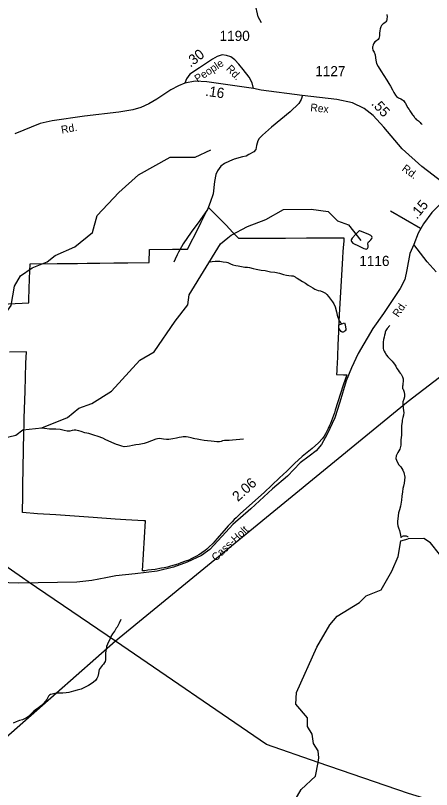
# Model space of a CAD drawing. Extents: x 2001466 to 2224147, y 644118 to 847247.
# Drawn here: x 2032407 to 2037525, y 669371 to 678885 of the extents above; entities that cross this region are included whole.
import ezdxf

# ---------------------------------------------------------------- set-up
doc = ezdxf.new("R2010")
doc.units = 0
for name, color, linetype in [('Exist Boundary Political City Limit New', 7, 'Continuous'), ('Exist Hydrographic Creek Single Shore', 7, 'Continuous'), ('Exist Hydrographic Misc Water Feature', 7, 'Continuous'), ('Exist Road Non-System Type 51', 7, 'Continuous'), ('Exist Road Secondary Mileage Hundredths English Label', 7, 'Continuous'), ('Exist Road Secondary Type 51 Attributed', 7, 'Continuous'), ('Exist Road Secondary Type 51 Label', 7, 'Continuous'), ('Exist Road Secondary Type 51 Number Label', 7, 'Continuous'), ('Exist Utilities Electrical Transmission Line', 7, 'Continuous'), ('Map Preparation Boundary City Limit Buffer Line', 7, 'Continuous')]:
    doc.layers.add(name, color=color, linetype=linetype)

msp = doc.modelspace()

# ---------------------------------------------------------------- linework, layer by layer
at = {"layer": 'Exist Boundary Political City Limit New'}
for points in [[(2032150.1, 675331.9), (2032570.6, 675351.3), (2032577.6, 675564.2), (2032579.2, 675608.3), (2032581.2, 675652.5), (2032588.4, 675832.8), (2032920.9, 675835.7), (2033170.2, 675837.9), (2033288, 675838.9), (2033445, 675840.2), (2033616.8, 675842.8), (2033788.5, 675845.2), (2034053.1, 675846.8), (2034057.5, 676010.3), (2034338.1, 676011.2), (2034412.5, 676011), (2034523.8, 676010.7), (2034656.9, 676273.8), (2034692.4, 676345.8), (2034781.1, 676524.9), (2035000, 676306.8), (2035082.4, 676217.2), (2035101.6, 676197.2)], [(2035101.6, 676197.2), (2035151.1, 676145.9), (2035232.5, 676147.4), (2035279.9, 676148.2), (2035730.8, 676149.4), (2035985.9, 676151.8), (2036075, 676151.7), (2036147.2, 676153), (2036238.4, 676152.8), (2036354.1, 676153.6), (2036385, 676153.5), (2036447.4, 676153.2), (2036446.6, 676141.7), (2036444.8, 676114.5), (2036438.8, 676028), (2036435.9, 675985.7), (2036430.5, 675903.8), (2036389.4, 675204.8), (2036384.8, 675113.8), (2036382.8, 675057), (2036380.8, 675000), (2036373.2, 674832), (2036371, 674779.9), (2036369.9, 674753.5), (2036369.8, 674750.8), (2036369.4, 674742.4), (2036366.8, 674679.1), (2036364.1, 674617.3), (2036360.4, 674540.9), (2036359.1, 674515.2), (2036357.6, 674470.4), (2036440.8, 674469), (2036442.1, 674469), (2036483.6, 674469.1), (2036437.8, 674340.8), (2036370.8, 674137.8), (2036340.8, 674033.2), (2036330.1, 674000), (2036319, 673967), (2036306.9, 673934.3), (2036294.4, 673901.8), (2036281, 673869.7), (2036267, 673837.8), (2036252.2, 673806.2), (2036237, 673775), (2036220.8, 673744.1), (2036204.2, 673713.5), (2036184.5, 673683.5), (2036136.5, 673630.5), (2036057.2, 673561.1), (2036018.1, 673528.9), (2035935, 673463.4), (2035841.5, 673379.3), (2035743.8, 673284.9), (2035656.2, 673200.5), (2035465.6, 673022.3), (2035175.2, 672761.7), (2035123.8, 672712.1), (2035097.2, 672688), (2035071.5, 672663), (2035059, 672650.1), (2035034.8, 672623.6), (2035023, 672610), (2035000, 672582.1), (2034890.5, 672455.7), (2034861.5, 672424.3), (2034837.6, 672399), (2034786.2, 672348.5), (2034759.6, 672323.8), (2034741.1, 672308.4), (2034701.9, 672278.5), (2034682.9, 672265.9), (2034663.5, 672254.1), (2034635.1, 672237.6), (2034569.6, 672204.4), (2034538.2, 672191.7), (2034498, 672177.5), (2034439.6, 672155.6), (2034403.4, 672142.7), (2034312.9, 672115), (2034276.8, 672105.4), (2034238, 672095.6), (2034205.6, 672089.5), (2034124, 672076.8), (2034078.8, 672070.1), (2034035.8, 672065.3), (2033998.1, 672059.7), (2033978.5, 672058), (2033971.2, 672056.9), (2034007.8, 672671.5), (2033987.2, 672672.8), (2033765.9, 672686.6), (2033631.9, 672695.6), (2033365.2, 672713.5), (2032904.9, 672745.6), (2032679.5, 672761.1), (2032494.5, 672773.8), (2032498.1, 672982.8), (2032499.9, 673106.6), (2032511.4, 673758.1)], [(2032511.4, 673758.1), (2032513.8, 673848.8), (2032516.1, 673935.4), (2032526, 674266.1), (2032537, 674611.6), (2032542, 674748.9), (2032335.8, 674746.7)]]:
    msp.add_lwpolyline(points, dxfattribs=at)
at = {"layer": 'Exist Hydrographic Creek Single Shore'}
for points in [[(2036129.8, 669704.3), (2036140.5, 669762), (2036131.5, 669844.3), (2036073.5, 669937.3), (2036056.5, 670052.5), (2035998.6, 670145.5), (2035998.6, 670253.8), (2035856.5, 670420.7), (2035864.5, 670561.7), (2036114.5, 671120.9), (2036272.6, 671393.3), (2036364.7, 671503), (2036639.6, 671671.3), (2036722.7, 671751.6), (2036905.6, 671826.6), (2037038.7, 672053.6), (2037113.7, 672235.8), (2037146.5, 672428.7), (2037236.1, 672453.3)], [(2037906.6, 671698), (2037831.6, 671732.4), (2037772.5, 671795.9), (2037722.5, 671997.1), (2037622.6, 672264.9), (2037513.6, 672404.9), (2037430.5, 672455.7), (2037236.1, 672453.3)], [(2034758.5, 668061.1), (2034941.6, 668228), (2034949.6, 668401.7), (2034982.6, 668453.5), (2035274.6, 668634.6), (2035449.5, 668854.2), (2035682.4, 668961), (2035923.6, 669369.5), (2036098.5, 669536.5), (2036129.8, 669704.3)]]:
    msp.add_lwpolyline(points, dxfattribs=at)
at = {"layer": 'Exist Hydrographic Misc Water Feature'}
msp.add_line((2032896.7, 675934.3), (2033137.7, 676040.6), dxfattribs=at)
for points in [[(2035435.8, 678792.5), (2035393.7, 678868.9), (2035318.9, 679201.7), (2035210.8, 679325.4), (2034976.9, 679451.5), (2034768.9, 679491.8), (2034376.9, 679466.9), (2034276.8, 679492), (2033843.9, 679408.9), (2033343.8, 679209), (2033026.8, 679274.6), (2032685.8, 679307.7), (2032218.9, 679382.8), (2031902.9, 679356.5), (2031718.8, 679291.3), (2031568.9, 679182.8), (2031377.8, 679157.2), (2031260.9, 679107), (2030952.9, 679090.3), (2030835.8, 679122.2), (2030419.8, 679097.8), (2030169.8, 678981.5), (2029908.9, 678947.4)], [(2036976.7, 678896.5), (2036978.8, 678868.5), (2036976.7, 678844), (2036974.7, 678832.6), (2036970.6, 678818.7), (2036964.8, 678808.2), (2036956.8, 678800.1), (2036938.6, 678788.2), (2036926.9, 678778.6), (2036910.9, 678760.1), (2036902.7, 678746.2), (2036892.9, 678720.2), (2036889, 678696.5), (2036887.1, 678666.2), (2036885.1, 678635.9), (2036881, 678616.3), (2036876.7, 678600.8), (2036869.1, 678590.3), (2036849.4, 678574.3), (2036829.3, 678559.9), (2036821.1, 678549.4), (2036813.3, 678536.5), (2036807.4, 678524.3), (2036801.4, 678508), (2036801.2, 678499.8), (2036799.4, 678481.8), (2036805.3, 678460.4), (2036821.3, 678432.1), (2036831.4, 678400), (2036837.5, 678366.2), (2036841.6, 678334.1), (2036845.7, 678314.3), (2036849.6, 678294.6), (2036869.7, 678256.5), (2036899.8, 678204.1), (2036938, 678145.9), (2036975.9, 678088.6), (2037002, 678050.3), (2037022, 678014.6), (2037044.2, 677972.4), (2037062.2, 677936.7), (2037080.3, 677906.8), (2037096.1, 677890.1), (2037120.1, 677872.4), (2037146.3, 677858.8), (2037168.3, 677848.5), (2037180.3, 677839.2), (2037190.2, 677829.1), (2037198.4, 677816.7), (2037204.3, 677805.1), (2037212.3, 677785.2), (2037228.3, 677757), (2037230.6, 677752.9)], [(2037230.6, 677752.9), (2037248.2, 677730.8), (2037260.3, 677712.8), (2037292.3, 677662.8), (2037298.5, 677654.8), (2037310.4, 677638.9), (2037316.5, 677630.9), (2037326.6, 677616.9), (2037338.4, 677607), (2037354.4, 677597), (2037366.5, 677589), (2037374.5, 677583), (2037384.6, 677571), (2037394.6, 677559), (2037402.6, 677551.1), (2037404.7, 677545.1)], [(2033137.7, 676040.6), (2033353.7, 676216.6), (2033411.7, 676425.3), (2033678.7, 676708.7), (2033919.8, 676926.9), (2034311.9, 677142.1), (2034619.9, 677142.3), (2034811.8, 677233.6)], [(2035018.7, 676149.9), (2035061.8, 676185.1), (2035261.7, 676292.6), (2035486.8, 676376.7), (2035703.8, 676500.2), (2036044.8, 676503.1), (2036253.7, 676475.9), (2036369.8, 676362), (2036503.7, 676310.1), (2036653.8, 676120)], [(2036601.9, 676203.1), (2036595.1, 676195.8), (2036549.4, 676145.9), (2036535.5, 676125.7), (2036535.5, 676115.8), (2036539.4, 676105.9), (2036557.4, 676085.9), (2036575.4, 676076.5), (2036619.5, 676055.9), (2036691.5, 676022.4), (2036707.5, 676016.4), (2036721.4, 676014.4), (2036737.6, 676022.3), (2036747.5, 676036.1), (2036747.5, 676056.6), (2036743.4, 676076.3), (2036747.5, 676092.7), (2036751.4, 676100.8), (2036761.4, 676112.1), (2036777.4, 676128.1), (2036789.3, 676144.3), (2036793.2, 676154.1), (2036791.2, 676166.4), (2036776.8, 676179), (2036753.2, 676192.6), (2036665.1, 676229.7), (2036641.1, 676235.9), (2036637.2, 676236), (2036625.1, 676228), (2036601.9, 676203.1)], [(2031871.5, 673621.6), (2031938.6, 673617.3), (2032413.7, 673725.7), (2032496.8, 673792.9), (2032730.7, 673817.7), (2033046.7, 673942.5), (2033188.6, 674057.8), (2033346.7, 674116.9), (2033588.7, 674266.2), (2033937.7, 674649.5), (2034112.8, 674750.9), (2034370.7, 675126.3), (2034529.6, 675326.5), (2034545.6, 675450.9), (2034928.7, 676076.4), (2035018.7, 676149.9)], [(2032001.4, 674668.6), (2032013.7, 674691.9), (2032038.7, 674783.3), (2032037.6, 675016.2), (2032262.8, 675192.1), (2032354.7, 675318.2), (2032395.7, 675556.9), (2032470.7, 675683.4), (2032612.8, 675782.2), (2032795.7, 675857.2), (2032895.8, 675933.9), (2032896.7, 675934.3)], [(2034803.6, 675857.4), (2034828.2, 675859.4), (2034864.3, 675863.5), (2034888.3, 675863), (2034920.3, 675863.2), (2034960.3, 675858.3), (2035002.3, 675851.7), (2035018.1, 675847.3), (2035052.3, 675833.5), (2035082.1, 675819.7), (2035116.1, 675810), (2035146.2, 675806.1), (2035188.1, 675799.5), (2035230.3, 675792.1), (2035260, 675789.8), (2035286.3, 675786.1), (2035330.2, 675773.6), (2035366.3, 675766.4), (2035430.2, 675756), (2035478.4, 675748.5), (2035510.4, 675740.5), (2035546.3, 675734.8), (2035598.4, 675730.5), (2035654.1, 675718.7), (2035706.2, 675702.9), (2035739.7, 675694.8), (2035770.4, 675688.5), (2035804.2, 675684.5), (2035824.3, 675683.2), (2035846.3, 675673), (2035858.2, 675665.4), (2035872.3, 675655.2), (2035905.3, 675634.9), (2035938.6, 675615.3), (2035974.4, 675593.3), (2036008.5, 675571.3), (2036064.7, 675535.7), (2036090.5, 675521.2), (2036132.5, 675505.5), (2036158.6, 675499.3), (2036186.7, 675489.7), (2036220.5, 675473.4), (2036238.8, 675455.8), (2036258.6, 675430), (2036282.6, 675395.9), (2036308.7, 675363.4), (2036322.8, 675340.1), (2036338.8, 675302.1), (2036356.9, 675240.2), (2036365.1, 675199.8), (2036372.9, 675175.9), (2036385.2, 675143.6), (2036393.2, 675127.9), (2036403, 675113.7), (2036409.1, 675106.3), (2036421, 675094.5)], [(2036421, 675094.5), (2036453.2, 675106.1), (2036461, 675083.8), (2036468.6, 675053.3), (2036473.1, 675034.4), (2036471.3, 675020.5), (2036463.3, 675010), (2036455.3, 675004.4), (2036447.3, 674998), (2036437.4, 674994.1), (2036427.4, 674994.3), (2036415.3, 675001.9), (2036403.4, 675016.1), (2036391.1, 675031.9), (2036385.2, 675058.3), (2036385.2, 675069.8), (2036385.2, 675082.1), (2036421, 675094.5)], [(2037011, 675072.6), (2036981, 675038.8), (2036965, 675011.3), (2036957, 674991), (2036953.2, 674981.1), (2036947.2, 674956.7), (2036941.3, 674930.5), (2036933.3, 674901.2), (2036931.4, 674869.2), (2036929.6, 674824.9), (2036929.6, 674815.1), (2036931.6, 674792.9), (2036935.5, 674777.2), (2036943.5, 674760.7), (2036955.6, 674736.7), (2036973, 674708.5), (2036985.8, 674691), (2037015.9, 674659.1), (2037041.7, 674637.3), (2037054.9, 674621.5), (2037070, 674599), (2037085.8, 674573.3), (2037100, 674547.5), (2037113.9, 674523.4), (2037126, 674505.2), (2037140, 674489.3), (2037152.1, 674475.2), (2037160, 674461), (2037170.1, 674445.2), (2037178.1, 674417.2), (2037176.2, 674393.4), (2037172.1, 674353.3), (2037170.3, 674339.4), (2037168.3, 674327.2), (2037166.4, 674311.6), (2037169.1, 674301.7), (2037174.4, 674291.8), (2037188.3, 674253.7), (2037192.9, 674225.8), (2037192.4, 674197.1), (2037186.5, 674169.3), (2037172.8, 674135.1), (2037170.7, 674099.1), (2037174.6, 674063.7), (2037181, 674025), (2037184.9, 674005.3), (2037180.8, 673973.4), (2037171.1, 673943.2), (2037165, 673909.7), (2037163.1, 673889.3), (2037161.1, 673871.3), (2037157, 673841.7), (2037155.1, 673811.5), (2037157.2, 673771.3), (2037155.3, 673725.3), (2037149.4, 673667.2), (2037149.6, 673621.3), (2037147.7, 673601.6), (2037135.4, 673553.5), (2037123.6, 673533.2), (2037109.8, 673513), (2037089.9, 673473.2), (2037087.9, 673439.6), (2037093.8, 673419), (2037108, 673389.2), (2037124.6, 673363.5), (2037145.9, 673335.1), (2037160, 673315.1), (2037171.9, 673294.4), (2037184, 673265.4), (2037196.3, 673211.9), (2037194.3, 673171.7), (2037190.2, 673137.3), (2037180.3, 673097.4), (2037172.6, 673068.8), (2037166.6, 673029.6), (2037160.5, 672975.6), (2037156.6, 672925.6), (2037142.8, 672855.3), (2037129.3, 672808.8), (2037120.9, 672771.3), (2037112.9, 672733.7), (2037109.2, 672697.7), (2037105.1, 672669.9), (2037105.3, 672639.6), (2037111.2, 672609.9), (2037119.4, 672586), (2037129.3, 672553.8), (2037139.3, 672517.5), (2037145.3, 672496), (2037149.6, 672473.7), (2037150.4, 672468.8)], [(2035211.8, 673677.9), (2035121.8, 673669.9), (2035075.9, 673664.3), (2035035.9, 673661.8), (2035005.8, 673661.6), (2034976.9, 673661.4), (2034955.7, 673656), (2034937.9, 673649.8), (2034915.8, 673645.4), (2034886, 673646), (2034849.9, 673650), (2034813.8, 673651.5), (2034770, 673655.7), (2034727.7, 673659), (2034682, 673668.9), (2034641.6, 673677.2), (2034611.9, 673681.1), (2034595.9, 673685.5), (2034567.8, 673695.1), (2034531.9, 673703.2), (2034508.5, 673706.2), (2034485.8, 673706.6), (2034472, 673706.9), (2034447.8, 673703.3), (2034420.1, 673697.3), (2034388, 673690.5), (2034342, 673680.8), (2034295.9, 673674.4), (2034264.1, 673672.6), (2034228, 673676.6), (2034202, 673680.4), (2034175.7, 673685), (2034135.3, 673676.8), (2034080, 673656.6), (2034026.2, 673636.4), (2033990.1, 673624), (2033970.3, 673620.2), (2033928.2, 673612.1), (2033888.2, 673606.4), (2033848.3, 673598.1), (2033811.3, 673590.7), (2033780.2, 673585.6), (2033745.7, 673584.6), (2033714.4, 673589.4), (2033668.2, 673605.9), (2033652.2, 673613.6), (2033592.1, 673637.8), (2033548.3, 673657.6), (2033520, 673669.6), (2033483.3, 673689.2), (2033426.3, 673710.9), (2033370.3, 673726.8), (2033308.1, 673745.3), (2033262, 673756.9), (2033214, 673772.6), (2033186.8, 673779.7), (2033166, 673785.1), (2033150.1, 673787), (2033128.1, 673786.7), (2033104.1, 673783.1), (2033078.1, 673774.5), (2033044, 673774.4), (2033006.1, 673784.2), (2032956.1, 673796.7), (2032906, 673800.2), (2032867.3, 673801.8), (2032824.2, 673801.9), (2032764.1, 673806.4), (2032714.5, 673812.3)], [(2037236.9, 672476.1), (2037233.5, 672477.8), (2037215.4, 672483.9), (2037203.5, 672485.8), (2037191.4, 672486.1), (2037175.4, 672483.9), (2037165.4, 672480), (2037155.3, 672473.6), (2037150.4, 672468.8)], [(2033701.8, 671461.9), (2033682.2, 671413.9), (2033658, 671367.7), (2033647.9, 671352.3), (2033638.1, 671336.1), (2033628, 671321.5), (2033626.2, 671318.2), (2033600.1, 671283.6), (2033580.5, 671251.9), (2033570.4, 671223.4), (2033556.3, 671194.2), (2033540.7, 671157.6), (2033528.4, 671127.5), (2033522.6, 671094), (2033516.7, 671051.4), (2033516.7, 671021.9), (2033514.8, 670966.2), (2033510.9, 670944.1), (2033502.9, 670932), (2033490.6, 670913.3), (2033472.8, 670895.7), (2033460.9, 670879.5), (2033451.1, 670863.3), (2033439, 670845.5), (2033433, 670823.5), (2033428.9, 670797.3), (2033421.1, 670761.4), (2033407.2, 670733.8), (2033393.2, 670711.9), (2033367.4, 670689.5), (2033339.3, 670667.9), (2033307.5, 670649.6), (2033263.4, 670627.6), (2033215.5, 670605.6), (2033167.5, 670593.5), (2033119.5, 670581.3), (2033065.6, 670565.2), (2033032.6, 670559.3), (2032991.5, 670555.2), (2032927.6, 670553.2), (2032893.7, 670550.7), (2032857.6, 670542.4), (2032839.8, 670538.6), (2032825.7, 670529), (2032813.6, 670517), (2032799.8, 670492.7), (2032791.6, 670478.9), (2032775.6, 670456.2), (2032748.8, 670424.8), (2032726, 670402.3), (2032689.9, 670374.4), (2032649.9, 670346.4), (2032634.6, 670332.8), (2032615.9, 670316.8), (2032612, 670312.7), (2032568.1, 670270.1), (2032544.1, 670252.6), (2032518.3, 670238.4), (2032494.3, 670228.2), (2032458.2, 670219.9), (2032416.4, 670201.9), (2032378.4, 670186.3)]]:
    msp.add_lwpolyline(points, dxfattribs=at)
at = {"layer": 'Exist Road Non-System Type 51'}
msp.add_line((2037391.4, 676265.4), (2037019.9, 676481.1), dxfattribs=at)
for points in [[(2035938.3, 677903.5), (2035921.8, 677851.6), (2035895.1, 677804), (2035787.9, 677699.3), (2035557.5, 677510), (2035446.3, 677415.4), (2035405.8, 677371.9), (2035387.5, 677344), (2035372.7, 677286.3), (2035364.1, 677236.3), (2035337.8, 677210.6), (2035277.4, 677175.5), (2035245.2, 677155.7), (2035199, 677146.3), (2035098.6, 677117.5), (2035038.4, 677094.3), (2034980, 677066.9), (2034931.7, 677031.5), (2034890.9, 676974.1), (2034870.4, 676928.3), (2034855.3, 676844.4), (2034837.3, 676690.8), (2034804.2, 676585), (2034769.1, 676501.5), (2034675.5, 676364.6), (2034569.6, 676222), (2034471.8, 676077.1), (2034412.6, 675975.7), (2034397.4, 675944.1)], [(2034397.4, 675944.1), (2034371.6, 675890.4), (2034355.1, 675852.5)]]:
    msp.add_lwpolyline(points, dxfattribs=at)
at = {"layer": 'Exist Road Secondary Type 51 Attributed'}
for points in [[(2035335.5, 677987), (2035317.9, 678056.8), (2035281.3, 678128.1), (2035210, 678222.6), (2035153.6, 678287.5), (2035105.7, 678338.3), (2035057.7, 678377.8), (2035004.2, 678393.3), (2034951.1, 678401.1), (2034888.7, 678378.8), (2034831.2, 678346.6), (2034670.1, 678242.6), (2034554.1, 678162.3), (2034509.5, 678104.3), (2034492.8, 678052.9)], [(2035335.5, 677987), (2035192, 678008.3), (2034761.6, 678068.5), (2034616.6, 678077.5), (2034492.8, 678052.9)], [(2034492.8, 678052.9), (2034412.5, 678021.7), (2034318.8, 677970.4), (2034144.8, 677854.3), (2034046.7, 677800.7), (2033948.5, 677753.9), (2033852.6, 677727.1), (2033680.6, 677698), (2033258.3, 677647.3), (2032857.2, 677588.1), (2032710.5, 677556.4), (2032399.5, 677429.1)], [(2037795.3, 676728.2), (2037668.7, 676828.6), (2037406.9, 677027.2), (2037163, 677244.8), (2036937.1, 677511), (2036806.3, 677654.7), (2036698.6, 677743.4), (2036552.9, 677813.1), (2036360.5, 677852), (2035935.2, 677901.6), (2035429.8, 677967.7), (2035335.5, 677987)], [(2037795.3, 676728.2), (2037530.4, 676462), (2037424.8, 676322.6), (2037359.4, 676210.6), (2037307.6, 676070.1)], [(2037307.6, 676070.1), (2037258, 675960.3), (2037222.7, 675757.5), (2037196.3, 675638.1), (2037137.7, 675528.3), (2036933.4, 675223), (2036802.6, 675037.1), (2036623.1, 674731.8), (2036541.3, 674555.4), (2036475.8, 674394.8), (2036397.7, 674130.7), (2036336.5, 673938.5), (2036242.6, 673739.9), (2036170.8, 673611), (2036107.4, 673532.8), (2036018.8, 673467.3), (2035909, 673384.9), (2035754.9, 673222.3), (2035568, 673065.9), (2035302, 672820.9), (2035080.3, 672628.6), (2034995.9, 672533.5), (2034798.5, 672322.3), (2034697.1, 672246.2), (2034519.8, 672163.8), (2034353, 672102.5), (2034150.3, 672056.1), (2033880.1, 672022.3), (2033641.5, 671999), (2033517, 671971.6), (2033347, 671939.9), (2033163.3, 671918.7), (2032449.7, 671906.1), (2031701.3, 671931.4)], [(2037580.5, 675732.1), (2037470.7, 675856.8), (2037307.6, 676070.1)]]:
    msp.add_lwpolyline(points, dxfattribs=at)
at = {"layer": 'Exist Utilities Electrical Transmission Line'}
for q in [(2032563, 671924.3), (2031623.5, 669424.4)]:
    msp.add_line((2033639.2, 671192.9), q, dxfattribs=at)
for points in [[(2037744.9, 674528.5), (2037236, 674141.1), (2033639.2, 671192.9)], [(2032563, 671924.3), (2032494.6, 671970.8), (2030876.5, 673096.5)], [(2036129.8, 669704.3), (2035494.1, 669922.4), (2033639.2, 671192.9)], [(2038428.2, 668960.1), (2037242.1, 669322.6), (2036129.8, 669704.3)]]:
    msp.add_lwpolyline(points, dxfattribs=at)
at = {"layer": 'Map Preparation Boundary City Limit Buffer Line'}
for points in [[(2032150.1, 675331.9), (2032570.6, 675351.3), (2032577.6, 675564.2), (2032579.2, 675608.3), (2032581.2, 675652.5), (2032588.4, 675832.8), (2032920.9, 675835.7), (2033170.2, 675837.9), (2033288, 675838.9), (2033445, 675840.2), (2033616.8, 675842.8), (2033788.5, 675845.2), (2034053.1, 675846.8), (2034057.5, 676010.3), (2034338.1, 676011.2), (2034412.5, 676011), (2034523.8, 676010.7), (2034656.9, 676273.8), (2034692.4, 676345.8), (2034781.1, 676524.9), (2035000, 676306.8), (2035082.4, 676217.2), (2035101.6, 676197.2)], [(2035101.6, 676197.2), (2035151.1, 676145.9), (2035232.5, 676147.4), (2035279.9, 676148.2), (2035730.8, 676149.4), (2035985.9, 676151.8), (2036075, 676151.7), (2036147.2, 676153), (2036238.4, 676152.8), (2036354.1, 676153.6), (2036385, 676153.5), (2036447.4, 676153.2), (2036446.6, 676141.7), (2036444.8, 676114.5), (2036438.8, 676028), (2036435.9, 675985.7), (2036430.5, 675903.8), (2036389.4, 675204.8), (2036384.8, 675113.8), (2036382.8, 675057), (2036380.8, 675000), (2036373.2, 674832), (2036371, 674779.9), (2036369.9, 674753.5), (2036369.8, 674750.8), (2036369.4, 674742.4), (2036366.8, 674679.1), (2036364.1, 674617.3), (2036360.4, 674540.9), (2036359.1, 674515.2), (2036357.6, 674470.4), (2036440.8, 674469), (2036442.1, 674469), (2036483.6, 674469.1), (2036437.8, 674340.8), (2036370.8, 674137.8), (2036340.8, 674033.2), (2036330.1, 674000), (2036319, 673967), (2036306.9, 673934.3), (2036294.4, 673901.8), (2036281, 673869.7), (2036267, 673837.8), (2036252.2, 673806.2), (2036237, 673775), (2036220.8, 673744.1), (2036204.2, 673713.5), (2036184.5, 673683.5), (2036136.5, 673630.5), (2036057.2, 673561.1), (2036018.1, 673528.9), (2035935, 673463.4), (2035841.5, 673379.3), (2035743.8, 673284.9), (2035656.2, 673200.5), (2035465.6, 673022.3), (2035175.2, 672761.7), (2035123.8, 672712.1), (2035097.2, 672688), (2035071.5, 672663), (2035059, 672650.1), (2035034.8, 672623.6), (2035023, 672610), (2035000, 672582.1), (2034890.5, 672455.7), (2034861.5, 672424.3), (2034837.6, 672399), (2034786.2, 672348.5), (2034759.6, 672323.8), (2034741.1, 672308.4), (2034701.9, 672278.5), (2034682.9, 672265.9), (2034663.5, 672254.1), (2034635.1, 672237.6), (2034569.6, 672204.4), (2034538.2, 672191.7), (2034498, 672177.5), (2034439.6, 672155.6), (2034403.4, 672142.7), (2034312.9, 672115), (2034276.8, 672105.4), (2034238, 672095.6), (2034205.6, 672089.5), (2034124, 672076.8), (2034078.8, 672070.1), (2034035.8, 672065.3), (2033998.1, 672059.7), (2033978.5, 672058), (2033971.2, 672056.9), (2034007.8, 672671.5), (2033987.2, 672672.8), (2033765.9, 672686.6), (2033631.9, 672695.6), (2033365.2, 672713.5), (2032904.9, 672745.6), (2032679.5, 672761.1), (2032494.5, 672773.8), (2032498.1, 672982.8), (2032499.9, 673106.6), (2032511.4, 673758.1)], [(2032511.4, 673758.1), (2032513.8, 673848.8), (2032516.1, 673935.4), (2032526, 674266.1), (2032537, 674611.6), (2032542, 674748.9), (2032335.8, 674746.7)]]:
    msp.add_lwpolyline(points, dxfattribs=at)

# ---------------------------------------------------------------- texts
at = {"layer": 'Exist Road Secondary Mileage Hundredths English Label'}
for s, rotation, p in [('.30', 37.76594, (2034559.9, 678241.6)), ('.16', 352.03212, (2034737.7, 677898.3)), ('.55', 312.33776, (2036778.3, 677796.3)), ('.15', 50.51458, (2037345.5, 676374)), ('2.06', 42.31439, (2035143.7, 672903.5))]:
    msp.add_text(s, height=125, rotation=rotation, dxfattribs=at).set_placement(p)
at = {"layer": 'Exist Road Secondary Type 51 Label'}
for s, rotation, p in [('People', 33.33501, (2034647.9, 678058.4)), ('Rd.', 313.72681, (2034991.9, 678223.9)), ('Rex', 354.19459, (2036030.8, 677709.4)), ('Rd.', 10.42059, (2032977.5, 677431.8)), ('Rd.', 323.7408, (2037152.8, 676985.7)), ('Rd.', 55.83504, (2037116.7, 675168.6)), ('Cass-Holt', 43.02213, (2034872.7, 672171.7))]:
    msp.add_text(s, height=95, rotation=rotation, dxfattribs=at).set_placement(p)
at = {"layer": 'Exist Road Secondary Type 51 Number Label'}
for s, p in [('1190', (2034917.8, 678572)), ('1127', (2036094.7, 678137.9)), ('1116', (2036636.5, 675805.4))]:
    msp.add_text(s, height=125, dxfattribs=at).set_placement(p)

doc.saveas('drawing.dxf')
